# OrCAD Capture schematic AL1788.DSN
size Custom; title: AL1788 - LOW STANDBY POWER PFC CONTROLLER; rev: 1.1; note: DS39401 Rev. 1 - 2
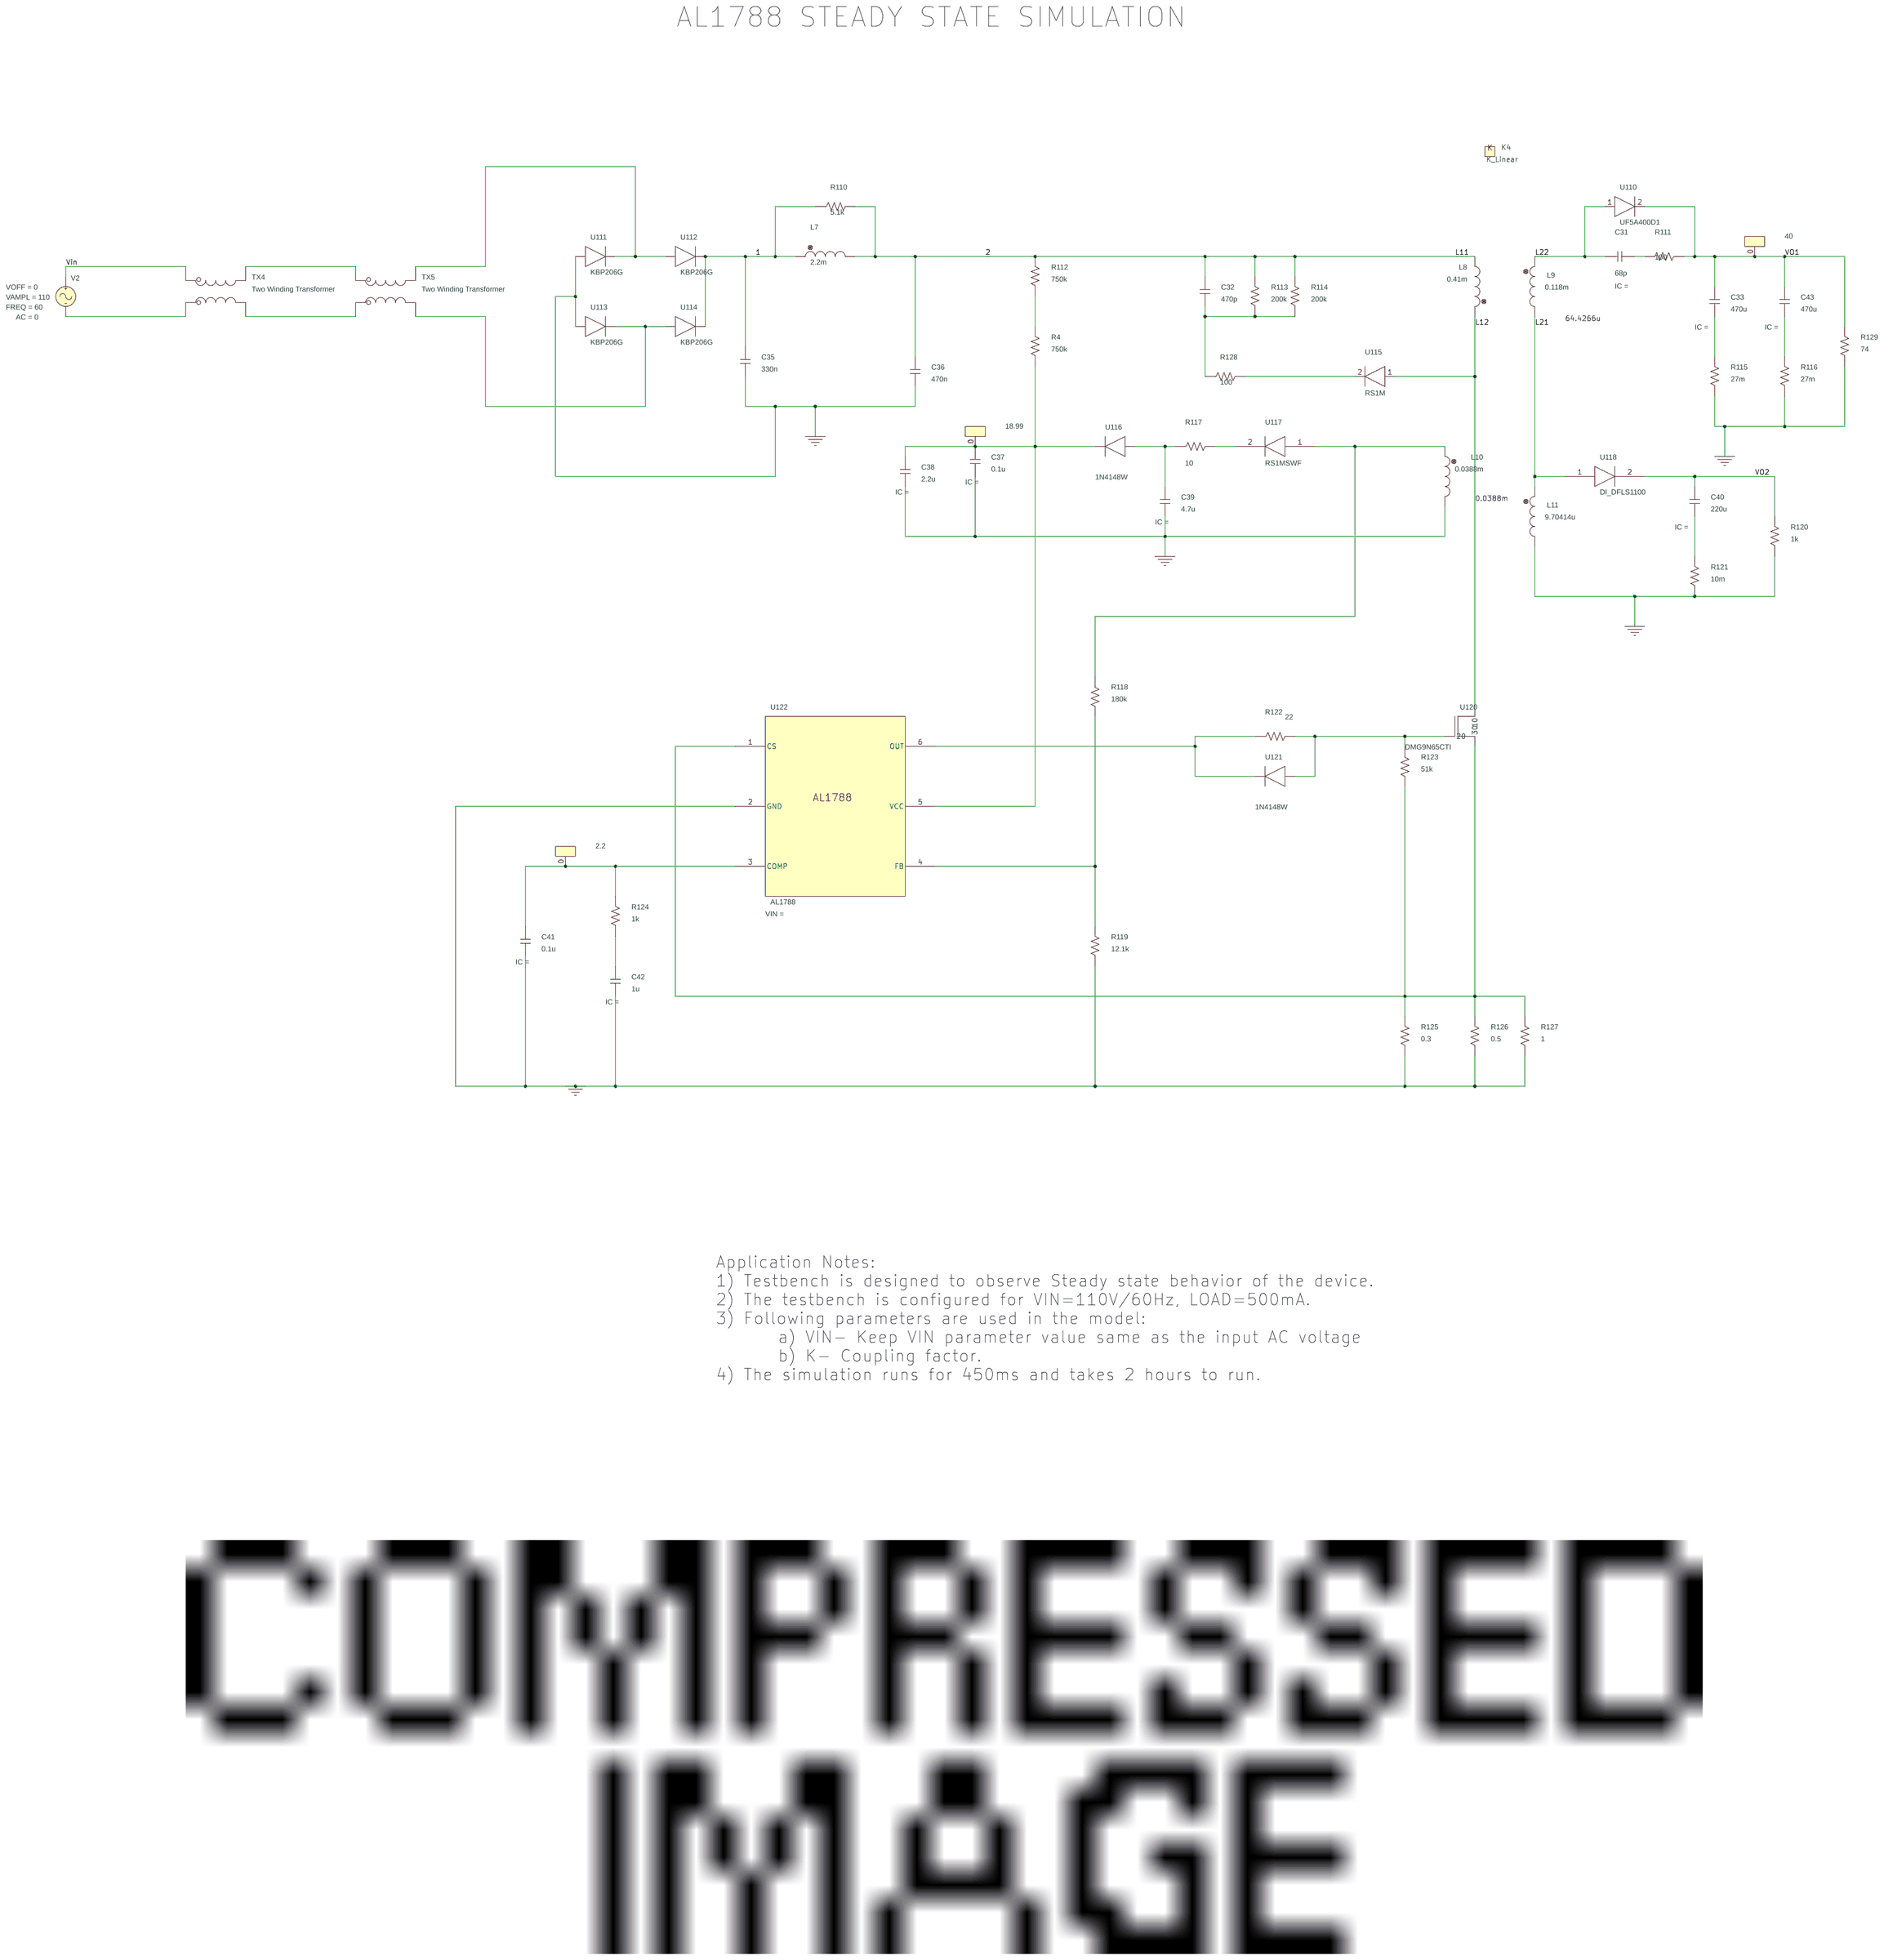
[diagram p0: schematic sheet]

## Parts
C31  68p  [RAD/CK05]
C32  470p  [RAD/CK05]
C33  470u  [RAD/CK05]
C35  330n  [RAD/CK05]
C36  470n  [RAD/CK05]
C37  0.1u  [RAD/CK05]
C38  2.2u  [RAD/CK05]
C39  4.7u  [RAD/CK05]
C40  220u  [RAD/CK05]
C41  0.1u  [RAD/CK05]
C42  1u  [RAD/CK05]
C43  470u  [RAD/CK05]
IC2  18.99
IC3  2.2
IC4  40
K4  K_Linear
L7  2.2m  [DISC/.350x.175/LS.200x.100/.034]
L8  0.41m  [DISC/.350x.175/LS.200x.100/.034]
L9  0.118m  [DISC/.350x.175/LS.200x.100/.034]
L10  0.0388m  [DISC/.350x.175/LS.200x.100/.034]
L11  9.70414u  [DISC/.350x.175/LS.200x.100/.034]
R4  750k  [AX/RC05]
R110  5.1k  [AX/RC05]
R111  100  [AX/RC05]
R112  750k  [AX/RC05]
R113  200k  [AX/RC05]
R114  200k  [AX/RC05]
R115  27m  [AX/RC05]
R116  27m  [AX/RC05]
R117  10  [AX/RC05]
R118  180k  [AX/RC05]
R119  12.1k  [AX/RC05]
R120  1k  [AX/RC05]
R121  10m  [AX/RC05]
R122  22  [AX/RC05]
R123  51k  [AX/RC05]
R124  1k  [AX/RC05]
R125  0.3  [AX/RC05]
R126  0.5  [AX/RC05]
R127  1  [AX/RC05]
R128  100  [AX/RC05]
R129  74  [AX/RC05]
TX4  Two Winding Transformer
TX5  Two Winding Transformer
U110  UF5A400D1
U111  KBP206G
U112  KBP206G
U113  KBP206G
U114  KBP206G
U115  RS1M
U116  1N4148W
U117  RS1MSWF
U118  DI_DFLS1100
U120  DMG9N65CTI
U121  1N4148W
U122  AL1788
V2  VSIN

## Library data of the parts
C31-C33 C35-C43 = C
IC2-IC4 = IC1
K4 = K_Linear: COUPLING: 0.9992; L1: L8; L2: L9; L3: L10; L4: L11
L7-L11 = L
R4 R110-R129 = R
TX4 = ST: AppProp: ST_Model,1m,10m,10m,1,100n
TX5 = ST: AppProp: ST_Model,30m,10m,10m,1,100n
U110 = UF5A400D1
U111-U114 = KBP206G
U115 = RS1M
U116 U121 = 1N4148W
U117 = RS1MSWF
U118 = DI_DFLS1100
U120 = DMG9N65CTI
U122 = AL1788
V2 = VSIN: AC: 0; AppProp: Sine$Voltage$0$-1; DC: 0; FREQ: 60; VAMPL: 110; VOFF: 0

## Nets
Vin: TX4.3 V2.1(+)
0: C35.1 C36.1 C37.2 C38.2 C39.2 C41.2 C42.2 L10.2 L11.2 R115.1 R116.1 R119.1 R120.1 R121.1 R125.1 R126.1 R127.1 R129.1 U111.1 U113.1 U122.2(GND)
1: C35.2 L7.1 R110.1 U112.2 U114.2
2: C32.2 C36.2 L7.2 L8.2 R110.2 R112.2 R113.2 R114.2
L12: L8.1 U115.1 U120.1(10)
L21: L9.2 L11.1 U118.1
L22: C31.1 L9.1 U110.1
VO1: C33.1 C43.1 IC4.0(+) R111.1 R129.2 U110.2
VO2: C40.1 R120.2 U118.2
N380958: TX5.4 U111.2 U112.1
N381270: C31.2 R111.2
N381330: TX4.4 TX5.3
N381572: R4.2 R112.1
N381614: C32.1 R113.1 R114.1 R128.1
N381618: TX4.1 V2.2(-)
N381624: TX4.2 TX5.1
N381630: TX5.2 U113.2 U114.1
N381712: C33.2 R115.2
N381718: C43.2 R116.2
N381812: C37.1 C38.1 IC2.0(+) R4.1 U116.2 U122.5(VCC)
N381914: R128.2 U115.2
N382098: C39.1 R117.1 U116.1
N382114: R117.2 U117.2
N382120: L10.1 R118.1 U117.1
N382338: C40.2 R121.2
N382522: R118.2 R119.2 U122.4(FB)
N382574: R122.1 U121.2 U122.6(OUT)
N382584: R122.2 R123.1 U120.2(20) U121.1
N382606: R123.2 R125.2 R126.2 R127.2 U120.3(30) U122.1(CS)
N382712: C41.1 IC3.0(+) R124.2 U122.3(COMP)
N382790: C42.1 R124.1

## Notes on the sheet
- AL1788 STEADY STATE SIMULATION
- 64.4266u
- 0.0388m
- Application Notes:
  1) Testbench is designed to observe Steady state behavior of the device.
  2) The testbench is configured for VIN=110V/60Hz, LOAD=500mA.
  3) Following parameters are used in the model:
         a) VIN- Keep VIN parameter value same as the input AC voltage
         b) K- Coupling factor.
  4) The simulation runs for 450ms and takes 2 hours to run.
